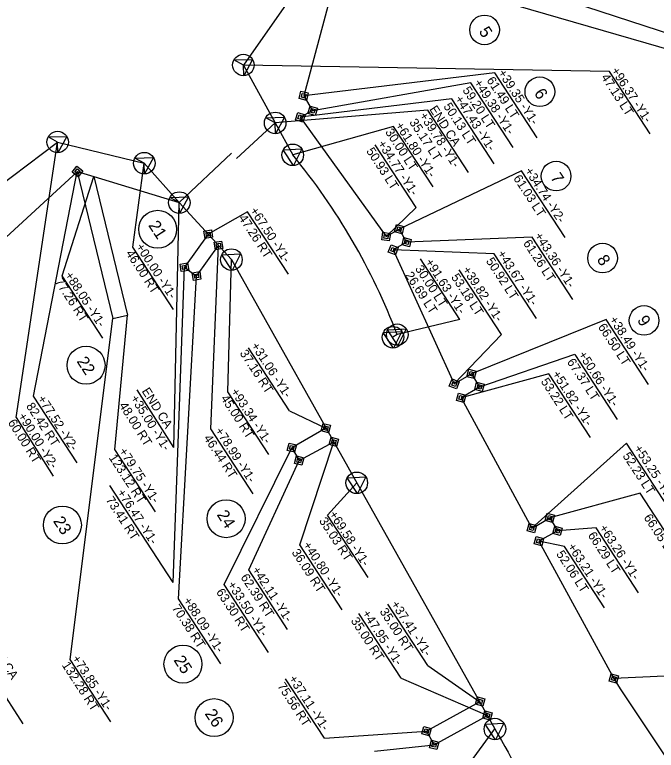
# Model space of a CAD drawing. Extents: x 1638966 to 1642158, y 841755 to 844938.
# Drawn here: x 1640306.3 to 1640735, y 843231.6 to 843723.1 of the extents above; entities that cross this region are included whole.
import ezdxf

# ---------------------------------------------------------------- set-up
doc = ezdxf.new("R2010")
doc.units = 0
for name, color, linetype in [('Exist Building', 7, 'Continuous'), ('Exist Guardrail Text', 7, 'Continuous'), ('Exist Other Culture Fence Line Text', 7, 'Continuous'), ('Exist Structure Major Deck Tunnel Box Culvert Text', 7, 'Continuous'), ('Exist Structure Minor Pipes CMP 18 Inch', 7, 'Continuous'), ('Exist Structure Minor Pipes CMP 18 Inch Text', 7, 'Continuous'), ('Exist Structure Minor Pipes CMP 24 Inch', 7, 'Continuous'), ('Exist Structure Minor Pipes RCP 24 Inch', 7, 'Continuous'), ('P_RDY_ROW_RW_CA_Lines', 7, 'Continuous'), ('Prop ROW Marker CA CELL', 7, 'Continuous'), ('Prop ROW Marker CELL', 7, 'Continuous')]:
    doc.layers.add(name, color=color, linetype=linetype)

msp = doc.modelspace()

# ---------------------------------------------------------------- linework, layer by layer
at = {"layer": 'Exist Building'}
for centre, radius in [((1640620.25, 843712.91), 9.91), ((1640657.19, 843671.65), 9.91), ((1640668.06, 843615.25), 9.91), ((1640401.81, 843579.7), 12.69), ((1640699.13, 843560.47), 9.91), ((1640726.79, 843518.8), 9.91), ((1640353.93, 843488.86), 12.69), ((1640447.56, 843386.31), 12.69), ((1640338.14, 843382.11), 12.69), ((1640418.7, 843289.14), 12.69), ((1640439.53, 843253.4), 12.69)]:
    msp.add_circle(centre, radius, dxfattribs=at)
at = {"layer": 'Exist Guardrail Text'}
for p, q in [((1640703.74, 843685.15), (1640459.09, 843689.48)), ((1640730.94, 843643.47), (1640703.74, 843685.15)), ((1640609.47, 843617.74), (1640582.27, 843659.42)), ((1640585.89, 843608.03), (1640559.48, 843648.51)), ((1640385.14, 843567.78), (1640392.88, 843623.89)), ((1640412.34, 843526.09), (1640385.14, 843567.78)), ((1640448.8, 843471.01), (1640451.09, 843559.48)), ((1640603.76, 843519.54), (1640577.34, 843560.02)), ((1640603.76, 843519.54), (1640561.9, 843509.3)), ((1640476, 843429.33), (1640448.8, 843471.01)), ((1640542.44, 843347.05), (1640515.24, 843388.74)), ((1640312.04, 843249.28), (1640271.05, 843312.1))]:
    msp.add_line(p, q, dxfattribs=at)
for points in [[(1640582.27, 843659.42), (1640480.35, 843650.79)], [(1640559.48, 843648.51), (1640492.08, 843629.44)], [(1640515.24, 843388.74), (1640534.84, 843410.29)], [(1640566.19, 843162.67), (1640627.16, 843245.8)]]:
    msp.add_lwpolyline(points, dxfattribs=at)
at = {"layer": 'Exist Other Culture Fence Line Text'}
for p, q in [((1640480.35, 843650.79), (1640492.08, 843629.44)), ((1640416.27, 843597.56), (1640451.09, 843559.48)), ((1640451.09, 843559.48), (1640627.16, 843245.8)), ((1640561.9, 843509.3), (1640559.02, 843507.57))]:
    msp.add_line(p, q, dxfattribs=at)
for centre, radius, start, end in [((1640160.09, 843356.15), 355, 34.9436, 34.9436), ((1640160.09, 843356.15), 430, 20.8649, 39.4616), ((1644817.57, 845597.08), 4805, 209.29724, 211.00035)]:
    msp.add_arc(centre, radius, start, end, dxfattribs=at)
at = {"layer": 'Exist Structure Major Deck Tunnel Box Culvert Text'}
for points in [[(1640480.35, 843650.79), (1640454.46, 843626.98)], [(1640416.27, 843597.56), (1640451.2, 843630.48)]]:
    msp.add_lwpolyline(points, dxfattribs=at)
at = {"layer": 'Exist Structure Minor Pipes CMP 18 Inch'}
for p, q in [((1640347.94, 843618.41), (1640371.82, 843520)), ((1640359.09, 843615), (1640381.54, 843522.35)), ((1640371.82, 843520), (1640381.54, 843522.35))]:
    msp.add_line(p, q, dxfattribs=at)
at = {"layer": 'Exist Structure Minor Pipes CMP 18 Inch Text'}
for p, q in [((1640781.19, 843688.57), (1640524.73, 843763.24)), ((1640788.22, 843695.73), (1640639.54, 843744.24)), ((1640338.03, 843548.66), (1640359.09, 843615)), ((1640365.23, 843506.98), (1640338.03, 843548.66)), ((1640343.42, 843292.29), (1640371.82, 843520)), ((1640373.23, 843432.53), (1640381.54, 843522.35)), ((1640400.43, 843390.84), (1640373.23, 843432.53)), ((1640370.62, 843250.6), (1640343.42, 843292.29))]:
    msp.add_line(p, q, dxfattribs=at)
at = {"layer": 'Exist Structure Minor Pipes CMP 24 Inch'}
for p, q in [((1640655.42, 843640.88), (1640627.13, 843684.24)), ((1640639.29, 843634.27), (1640611, 843677.63)), ((1640626.57, 843623.44), (1640598.28, 843666.8)), ((1640574.44, 843594.38), (1640547.24, 843636.06)), ((1640318.93, 843468.16), (1640347.94, 843618.41)), ((1640674.05, 843574.15), (1640644.98, 843618.71)), ((1640489.14, 843549.69), (1640461.94, 843591.37)), ((1640679.25, 843532.82), (1640652.05, 843574.51)), ((1640437.27, 843446.31), (1640442.46, 843568.92)), ((1640654.96, 843520.05), (1640626.67, 843563.41)), ((1640412.27, 843343.59), (1640419.69, 843554.33)), ((1640631.66, 843509.31), (1640603.37, 843552.67)), ((1640415.77, 843332.8), (1640427.78, 843548.48)), ((1640729.82, 843476.03), (1640701.53, 843519.39)), ((1640489.93, 843458.32), (1640462.42, 843500.47)), ((1640709.07, 843452.62), (1640680.78, 843495.98)), ((1640691.03, 843440.49), (1640663.14, 843483.23)), ((1640348.01, 843423.6), (1640318.93, 843468.16)), ((1640489.93, 843458.32), (1640514.16, 843446.9)), ((1640465.56, 843402.95), (1640437.27, 843446.31)), ((1640715.06, 843436.77), (1640651.87, 843380.03)), ((1640745.49, 843390.15), (1640715.06, 843436.77)), ((1640446.25, 843342.45), (1640491.39, 843433.78)), ((1640462.71, 843352.08), (1640496.39, 843425.11)), ((1640412.27, 843343.59), (1640369.87, 843408.56)), ((1640724.15, 843403.3), (1640663.85, 843386.92)), ((1640760.24, 843347.99), (1640724.15, 843403.3)), ((1640723.04, 843336.79), (1640694.74, 843380.15)), ((1640525.12, 843325.39), (1640496.83, 843368.75)), ((1640700.34, 843326.71), (1640673.61, 843367.66)), ((1640488.65, 843312.33), (1640462.71, 843352.08)), ((1640475.95, 843296.93), (1640446.25, 843342.45)), ((1640444.06, 843289.44), (1640415.77, 843332.8)), ((1640582.37, 843288.25), (1640555.65, 843329.2)), ((1640564.61, 843279.7), (1640536.32, 843323.06)), ((1640513.22, 843239.64), (1640487.28, 843279.39)), ((1640546.77, 843231), (1640586.56, 843235.12))]:
    msp.add_line(p, q, dxfattribs=at)
for points in [[(1640627.13, 843684.24), (1640499.38, 843668.98)], [(1640611, 843677.63), (1640505.38, 843658.87)], [(1640598.28, 843666.8), (1640497.12, 843654.53)], [(1640644.98, 843618.71), (1640563.27, 843579.75)], [(1640574.44, 843594.38), (1640554.45, 843574.83)], [(1640461.94, 843591.37), (1640435.59, 843576.43)], [(1640652.05, 843574.51), (1640568.19, 843571.13)], [(1640626.67, 843563.41), (1640559.21, 843566)], [(1640701.53, 843519.39), (1640611.58, 843483.05)], [(1640631.66, 843509.31), (1640599.98, 843476.41)], [(1640680.44, 843495.98), (1640616.76, 843474.3)], [(1640663.14, 843483.23), (1640604.56, 843467.07)], [(1640496.83, 843368.75), (1640519.55, 843437.67)], [(1640694.74, 843380.15), (1640669.03, 843378.18)], [(1640673.61, 843367.66), (1640656.59, 843371.25)], [(1640582.37, 843288.25), (1640616.98, 843263.95)], [(1640564.61, 843279.7), (1640622.14, 843254.75)], [(1640740.55, 843281.01), (1640706.65, 843279.59)], [(1640513.22, 843239.64), (1640581.46, 843244.36)]]:
    msp.add_lwpolyline(points, dxfattribs=at)
at = {"layer": 'Exist Structure Minor Pipes RCP 24 Inch'}
for p, q in [((1640528.84, 843778.51), (1640499.38, 843668.98)), ((1640499.38, 843668.98), (1640499.38, 843668.98)), ((1640499.38, 843668.98), (1640505.38, 843658.87)), ((1640505.38, 843658.87), (1640497.12, 843654.53)), ((1640505.38, 843658.87), (1640505.38, 843658.87)), ((1640497.12, 843654.53), (1640497.12, 843654.53)), ((1640497.12, 843654.53), (1640554.45, 843574.83)), ((1640269.63, 843546.21), (1640348.28, 843618.3)), ((1640347.94, 843618.41), (1640359.09, 843615)), ((1640348.28, 843618.3), (1640348.28, 843618.3)), ((1640359.09, 843615), (1640416.27, 843597.56)), ((1640554.45, 843574.83), (1640563.27, 843579.75)), ((1640563.27, 843579.75), (1640563.27, 843579.75)), ((1640563.27, 843579.75), (1640568.19, 843571.13)), ((1640435.59, 843576.43), (1640435.59, 843576.43)), ((1640554.45, 843574.83), (1640554.45, 843574.83)), ((1640442.46, 843568.92), (1640442.46, 843568.92)), ((1640568.19, 843571.13), (1640559.21, 843566)), ((1640568.19, 843571.13), (1640568.19, 843571.13)), ((1640559.21, 843566), (1640559.21, 843566)), ((1640559.21, 843566), (1640599.98, 843476.41)), ((1640419.69, 843554.33), (1640419.69, 843554.33)), ((1640427.78, 843548.48), (1640427.78, 843548.48)), ((1640599.98, 843476.41), (1640611.58, 843483.05)), ((1640611.58, 843483.05), (1640611.58, 843483.05)), ((1640611.58, 843483.05), (1640616.76, 843474.3)), ((1640599.98, 843476.41), (1640599.98, 843476.41)), ((1640616.76, 843474.3), (1640604.56, 843467.07)), ((1640616.77, 843474.5), (1640616.77, 843474.5)), ((1640604.56, 843467.07), (1640604.56, 843467.07)), ((1640604.56, 843467.07), (1640651.87, 843380.03)), ((1640514.16, 843446.9), (1640491.39, 843433.78)), ((1640514.16, 843446.9), (1640514.16, 843446.9)), ((1640496.39, 843425.11), (1640519.55, 843437.67)), ((1640519.55, 843437.67), (1640519.55, 843437.67)), ((1640491.39, 843433.78), (1640496.39, 843425.11)), ((1640491.39, 843433.78), (1640491.39, 843433.78)), ((1640496.39, 843425.11), (1640496.39, 843425.11)), ((1640655.09, 843381.73), (1640663.85, 843386.92)), ((1640663.85, 843386.92), (1640663.85, 843386.92)), ((1640663.85, 843386.92), (1640669.03, 843378.18)), ((1640651.87, 843380.03), (1640655.09, 843381.73)), ((1640651.87, 843380.03), (1640651.87, 843380.03)), ((1640669.03, 843378.18), (1640656.59, 843371.25)), ((1640669.03, 843378.18), (1640669.03, 843378.18)), ((1640656.59, 843371.25), (1640656.59, 843371.25)), ((1640656.59, 843371.25), (1640706.65, 843279.59)), ((1640706.65, 843279.5), (1640706.65, 843279.5)), ((1640617.32, 843264.14), (1640617.32, 843264.14)), ((1640622.14, 843254.75), (1640622.14, 843254.75)), ((1640581.46, 843244.36), (1640581.46, 843244.36)), ((1640586.56, 843235.12), (1640586.56, 843235.12))]:
    msp.add_line(p, q, dxfattribs=at)
for points in [[(1640497.54, 843672.07), (1640502.47, 843670.82), (1640501.21, 843665.88), (1640496.28, 843667.14)], [(1640498.46, 843670.53), (1640500.92, 843669.9), (1640500.3, 843667.43), (1640497.83, 843668.06)], [(1640503.71, 843662.05), (1640508.57, 843660.54), (1640507.06, 843655.68), (1640502.2, 843657.19)], [(1640495.45, 843657.72), (1640500.31, 843656.2), (1640498.79, 843651.35), (1640493.93, 843652.86)], [(1640496.29, 843656.13), (1640498.72, 843655.37), (1640497.96, 843652.94), (1640495.53, 843653.7)], [(1640504.55, 843660.46), (1640506.98, 843659.7), (1640506.22, 843657.27), (1640503.79, 843658.03)], [(1640347.8, 843621.87), (1640351.85, 843618.79), (1640348.76, 843614.74), (1640344.71, 843617.82)], [(1640348.04, 843620.09), (1640350.06, 843618.54), (1640348.52, 843616.52), (1640346.5, 843618.06)], [(1640561.45, 843582.86), (1640566.37, 843581.57), (1640565.08, 843576.65), (1640560.16, 843577.93)], [(1640432.67, 843578.53), (1640437.69, 843579.36), (1640438.52, 843574.34), (1640433.49, 843573.51)], [(1640434.13, 843577.48), (1640436.64, 843577.9), (1640437.05, 843575.38), (1640434.54, 843574.97)], [(1640552.35, 843577.76), (1640557.38, 843576.94), (1640556.55, 843571.91), (1640551.53, 843572.73)], [(1640562.36, 843581.31), (1640564.82, 843580.66), (1640564.18, 843578.2), (1640561.71, 843578.84)], [(1640553.4, 843576.3), (1640555.91, 843575.88), (1640555.5, 843573.37), (1640552.99, 843573.78)], [(1640566.37, 843574.23), (1640571.3, 843572.94), (1640570.01, 843568.02), (1640565.08, 843569.31)], [(1640567.28, 843572.68), (1640569.74, 843572.03), (1640569.1, 843569.57), (1640566.64, 843570.22)], [(1640439.53, 843571.02), (1640444.56, 843571.85), (1640445.38, 843566.83), (1640440.36, 843566)], [(1640441, 843569.97), (1640443.51, 843570.39), (1640443.92, 843567.88), (1640441.41, 843567.46)], [(1640557.73, 843569.28), (1640562.49, 843567.48), (1640560.69, 843562.72), (1640555.93, 843564.52)], [(1640558.47, 843567.64), (1640560.85, 843566.74), (1640559.95, 843564.36), (1640557.57, 843565.26)], [(1640416.76, 843556.43), (1640421.78, 843557.26), (1640422.61, 843552.24), (1640417.59, 843551.41)], [(1640418.22, 843555.38), (1640420.73, 843555.8), (1640421.15, 843553.28), (1640418.64, 843552.87)], [(1640424.86, 843550.58), (1640429.88, 843551.4), (1640430.71, 843546.38), (1640425.69, 843545.55)], [(1640426.32, 843549.53), (1640428.83, 843549.94), (1640429.25, 843547.43), (1640426.73, 843547.02)], [(1640609.76, 843486.16), (1640614.68, 843484.87), (1640613.4, 843479.95), (1640608.47, 843481.23)], [(1640610.67, 843484.6), (1640613.13, 843483.96), (1640612.49, 843481.5), (1640610.02, 843482.14)], [(1640598.49, 843479.69), (1640603.26, 843477.89), (1640601.46, 843473.13), (1640596.7, 843474.92)], [(1640599.24, 843478.05), (1640601.62, 843477.15), (1640600.72, 843474.77), (1640598.34, 843475.66)], [(1640614.95, 843477.61), (1640619.88, 843476.32), (1640618.59, 843471.4), (1640613.67, 843472.68)], [(1640615.86, 843476.06), (1640618.33, 843475.41), (1640617.68, 843472.95), (1640615.22, 843473.59)], [(1640602.74, 843470.18), (1640607.66, 843468.89), (1640606.38, 843463.97), (1640601.45, 843465.25)], [(1640603.65, 843468.63), (1640606.11, 843467.98), (1640605.47, 843465.52), (1640603, 843466.16)], [(1640512.34, 843450.01), (1640517.27, 843448.72), (1640515.98, 843443.8), (1640511.06, 843445.08)], [(1640513.25, 843448.46), (1640515.72, 843447.81), (1640515.07, 843445.35), (1640512.61, 843445.99)], [(1640517.73, 843440.77), (1640522.66, 843439.49), (1640521.37, 843434.56), (1640516.45, 843435.85)], [(1640489.57, 843436.88), (1640494.5, 843435.6), (1640493.21, 843430.67), (1640488.29, 843431.96)], [(1640490.48, 843435.33), (1640492.95, 843434.69), (1640492.3, 843432.23), (1640489.84, 843432.87)], [(1640518.64, 843439.22), (1640521.1, 843438.58), (1640520.46, 843436.11), (1640518, 843436.76)], [(1640494.57, 843428.22), (1640499.5, 843426.93), (1640498.21, 843422.01), (1640493.28, 843423.29)], [(1640495.48, 843426.66), (1640497.94, 843426.02), (1640497.3, 843423.56), (1640494.84, 843424.2)], [(1640662.03, 843390.03), (1640666.96, 843388.74), (1640665.67, 843383.82), (1640660.75, 843385.1)], [(1640662.94, 843388.48), (1640665.41, 843387.83), (1640664.76, 843385.37), (1640662.3, 843386.01)], [(1640650.05, 843383.13), (1640654.98, 843381.85), (1640653.69, 843376.92), (1640648.77, 843378.21)], [(1640650.96, 843381.58), (1640653.43, 843380.94), (1640652.78, 843378.47), (1640650.32, 843379.12)], [(1640667.21, 843381.29), (1640672.14, 843380), (1640670.85, 843375.07), (1640665.92, 843376.36)], [(1640668.12, 843379.73), (1640670.58, 843379.09), (1640669.94, 843376.63), (1640667.48, 843377.27)], [(1640654.78, 843374.36), (1640659.7, 843373.07), (1640658.41, 843368.15), (1640653.49, 843369.43)], [(1640655.68, 843372.81), (1640658.15, 843372.16), (1640657.5, 843369.7), (1640655.04, 843370.34)], [(1640704.83, 843282.61), (1640709.76, 843281.32), (1640708.47, 843276.4), (1640703.55, 843277.68)], [(1640705.74, 843281.05), (1640708.21, 843280.41), (1640707.56, 843277.95), (1640705.1, 843278.59)], [(1640615.5, 843267.25), (1640620.43, 843265.96), (1640619.14, 843261.03), (1640614.22, 843262.32)], [(1640616.41, 843265.69), (1640618.88, 843265.05), (1640618.23, 843262.59), (1640615.77, 843263.23)], [(1640620.32, 843257.86), (1640625.24, 843256.57), (1640623.96, 843251.65), (1640619.03, 843252.93)], [(1640621.23, 843256.3), (1640623.69, 843255.66), (1640623.05, 843253.2), (1640620.59, 843253.84)], [(1640579.64, 843247.46), (1640584.57, 843246.18), (1640583.28, 843241.25), (1640578.36, 843242.54)], [(1640580.55, 843245.91), (1640583.01, 843245.27), (1640582.37, 843242.81), (1640579.91, 843243.45)], [(1640584.74, 843238.23), (1640589.66, 843236.94), (1640588.37, 843232.02), (1640583.45, 843233.3)], [(1640585.65, 843236.68), (1640588.11, 843236.03), (1640587.47, 843233.57), (1640585, 843234.21)]]:
    msp.add_lwpolyline(points, close=True, dxfattribs=at)
for points in [[(1640435.59, 843576.43), (1640419.69, 843554.33), (1640427.78, 843548.48), (1640442.46, 843568.92)], [(1640706.65, 843279.5), (1640710.92, 843272.69), (1640777.02, 843173.29), (1640955.29, 842892.74)], [(1640616.98, 843263.95), (1640581.46, 843244.36), (1640586.56, 843235.12), (1640622.14, 843254.75)]]:
    msp.add_lwpolyline(points, dxfattribs=at)
at = {"layer": 'P_RDY_ROW_RW_CA_Lines'}
for p, q in [((1640577.95, 843859.33), (1640459.09, 843689.48)), ((1640459.09, 843689.48), (1640480.35, 843650.79)), ((1640293.13, 843606.47), (1640334.97, 843638.04)), ((1640334.97, 843638.04), (1640392.88, 843623.89)), ((1640392.88, 843623.89), (1640416.27, 843597.56))]:
    msp.add_line(p, q, dxfattribs=at)
at = {"layer": 'Prop ROW Marker CA CELL'}
for p, q in [((1640307.3, 843453.93), (1640334.97, 843638.04)), ((1640412.5, 843433.97), (1640416.27, 843597.56)), ((1640412.5, 843433.97), (1640388.17, 843472.43)), ((1640307.3, 843453.93), (1640332.06, 843414.79))]:
    msp.add_line(p, q, dxfattribs=at)
at = {"layer": 'Prop ROW Marker CELL'}
for p, q in [((1640452.75, 843692.91), (1640465.22, 843693.26)), ((1640459.09, 843689.48), (1640452.75, 843692.91)), ((1640465.22, 843693.26), (1640459.31, 843682.27)), ((1640459.31, 843682.27), (1640459.09, 843689.48)), ((1640474, 843654.22), (1640486.47, 843654.58)), ((1640480.35, 843650.79), (1640474, 843654.22)), ((1640486.47, 843654.58), (1640480.57, 843643.58)), ((1640480.57, 843643.58), (1640480.35, 843650.79)), ((1640328.63, 843641.47), (1640341.1, 843641.82)), ((1640334.97, 843638.04), (1640328.63, 843641.47)), ((1640341.1, 843641.82), (1640335.19, 843630.83)), ((1640335.19, 843630.83), (1640334.97, 843638.04)), ((1640386.54, 843627.32), (1640399.01, 843627.67)), ((1640392.88, 843623.89), (1640386.54, 843627.32)), ((1640399.01, 843627.67), (1640393.1, 843616.68)), ((1640492.08, 843629.44), (1640492.08, 843629.44)), ((1640393.1, 843616.68), (1640392.88, 843623.89)), ((1640409.92, 843600.99), (1640422.4, 843601.34)), ((1640416.27, 843597.56), (1640409.92, 843600.99)), ((1640416.49, 843590.35), (1640416.27, 843597.56)), ((1640422.4, 843601.34), (1640416.49, 843590.35)), ((1640451.09, 843559.48), (1640451.09, 843559.48)), ((1640561.9, 843509.3), (1640561.9, 843509.3)), ((1640559.02, 843507.57), (1640559.02, 843507.57)), ((1640534.84, 843410.29), (1640534.84, 843410.29)), ((1640627.16, 843245.8), (1640627.16, 843245.8))]:
    msp.add_line(p, q, dxfattribs=at)
for points in [[(1640485.65, 843632.71), (1640498.11, 843633.38), (1640492.48, 843622.24)], [(1640444.66, 843562.75), (1640457.12, 843563.42), (1640451.49, 843552.28)], [(1640552.59, 843510.84), (1640565.05, 843511.5), (1640559.42, 843500.37)], [(1640555.47, 843512.57), (1640567.93, 843513.24), (1640562.3, 843502.1)], [(1640528.41, 843413.56), (1640540.87, 843414.22), (1640535.24, 843403.09)], [(1640620.73, 843249.07), (1640633.19, 843249.74), (1640627.56, 843238.6)]]:
    msp.add_lwpolyline(points, close=True, dxfattribs=at)
for centre in [(1640459.09, 843689.48), (1640480.35, 843650.79), (1640334.97, 843638.04), (1640492.08, 843629.44), (1640392.88, 843623.89), (1640416.27, 843597.56), (1640451.09, 843559.48), (1640559.02, 843507.57), (1640561.9, 843509.3), (1640534.84, 843410.29), (1640627.16, 843245.8)]:
    msp.add_circle(centre, 7.2, dxfattribs=at)

# ---------------------------------------------------------------- texts
at = {"layer": 'Exist Building'}
for s, p in [('5', (1640616.1, 843711.94)), ('6', (1640653.04, 843670.68)), ('7', (1640663.91, 843614.29)), ('21', (1640395.3, 843582.36)), ('8', (1640694.98, 843559.5)), ('9', (1640721.9, 843518.98)), ('22', (1640347.42, 843491.52)), ('24', (1640441.05, 843388.97)), ('23', (1640331.64, 843384.77)), ('25', (1640412.19, 843291.8)), ('26', (1640433.02, 843256.06))]:
    msp.add_text(s, height=8, rotation=303.0906, dxfattribs=at).set_placement(p)
at = {"layer": 'Exist Guardrail Text'}
for s, p in [('+96.37 -Y1-', (1640704.57, 843685.7)), ('47.13 LT', (1640697.87, 843681.33)), ('END CA', (1640583.11, 843659.97)), ('+39.78 -Y1-', (1640576.41, 843655.6)), ('35.17 LT', (1640569.71, 843651.23)), ('30.00 LT', (1640553.62, 843644.69)), ('+61.80 -Y1-', (1640560.32, 843649.06)), ('+00.00 -Y1-', (1640386.96, 843567.98)), ('46.00 RT', (1640380.26, 843563.6)), ('+91.63 -Y1-', (1640580.26, 843557.77)), ('30.00 LT', (1640573.56, 843553.4)), ('26.69 LT', (1640566.86, 843549.03)), ('+93.34 -Y1-', (1640450.37, 843471.16)), ('45.00 RT', (1640443.67, 843466.79)), ('+69.58 -Y1-', (1640516.08, 843389.28)), ('35.03 RT', (1640509.38, 843384.91)), ('BEGIN CA', (1640283.14, 843310.44))]:
    msp.add_text(s, height=6, rotation=303.1259, dxfattribs=at).set_placement(p)
at = {"layer": 'Exist Structure Minor Pipes CMP 18 Inch Text'}
for s, p in [('+88.05 -Y1-', (1640339.5, 843549.05)), ('77.26 RT', (1640332.8, 843544.68)), ('+79.75 -Y1-', (1640375.62, 843431.44)), ('123.12 RT', (1640368.92, 843427.07)), ('+73.85 -Y1-', (1640344.26, 843292.83)), ('132.28 RT', (1640337.56, 843288.46))]:
    msp.add_text(s, height=6, rotation=303.1259, dxfattribs=at).set_placement(p)
at = {"layer": 'Exist Structure Minor Pipes CMP 24 Inch'}
for s, p in [('+39.35 -Y1-', (1640628.93, 843684.22)), ('61.49 LT', (1640621.4, 843679.31)), ('+49.38 -Y1-', (1640612.8, 843677.62)), ('59.20 LT', (1640605.26, 843672.7)), ('+47.43 -Y1-', (1640600.08, 843666.78)), ('50.13 LT', (1640592.54, 843661.87)), ('+34.77 -Y1-', (1640548.5, 843636.88)), ('50.93 LT', (1640540.96, 843631.97)), ('+34.74 -Y2-', (1640646.78, 843618.69)), ('61.03 LT', (1640639.24, 843613.77)), ('+67.50 -Y1-', (1640463.2, 843592.19)), ('47.26 RT', (1640455.66, 843587.28)), ('61.26 LT', (1640645.77, 843570.41)), ('+43.36 -Y1-', (1640653.31, 843575.33)), ('+43.67 -Y1-', (1640628.47, 843563.39)), ('50.92 LT', (1640620.93, 843558.47)), ('+39.82 -Y1-', (1640605.17, 843552.65)), ('53.18 LT', (1640597.63, 843547.73)), ('+38.49 -Y1-', (1640703.33, 843519.37)), ('66.50 LT', (1640695.79, 843514.45)), ('37.16 RT', (1640456.4, 843496.91)), ('+31.06 -Y1-', (1640463.94, 843501.82)), ('+50.66 -Y1-', (1640682.58, 843495.96)), ('67.37 LT', (1640675.05, 843491.04)), ('+51.82 -Y1-', (1640665.13, 843482.92)), ('53.22 LT', (1640657.6, 843478)), ('+77.52 -Y2-', (1640321.18, 843466.44)), ('82.42 RT', (1640313.64, 843461.52)), ('+78.99 -Y1-', (1640439.83, 843445.1)), ('46.44 RT', (1640432.29, 843440.19)), ('+53.25 -Y1-', (1640719.79, 843433.24)), ('52.23 LT', (1640712.25, 843428.32)), ('+76.47 -Y1-', (1640374.4, 843403.8)), ('73.41 RT', (1640366.87, 843398.89)), ('66.05 LT', (1640726.36, 843387.11)), ('+63.26 -Y1-', (1640696.55, 843380.13)), ('66.29 LT', (1640689.01, 843375.21)), ('36.09 RT', (1640491.09, 843363.81)), ('+40.80 -Y1-', (1640498.63, 843368.73)), ('+63.21 -Y1-', (1640675.42, 843367.64)), ('52.06 LT', (1640667.88, 843362.72)), ('+42.11 -Y1-', (1640464.52, 843352.06)), ('62.39 RT', (1640456.98, 843347.15)), ('+33.50 -Y1-', (1640448.17, 843342.22)), ('63.30 RT', (1640440.63, 843337.31)), ('+88.09 -Y1-', (1640418.62, 843331.55)), ('70.38 RT', (1640411.08, 843326.63)), ('35.00 RT', (1640549.91, 843324.27)), ('+37.41 -Y1-', (1640557.45, 843329.18)), ('+47.95 -Y1-', (1640538.12, 843323.04)), ('35.00 RT', (1640530.58, 843318.12)), ('75.56 RT', (1640481.54, 843274.45)), ('+37.11 -Y1-', (1640489.08, 843279.37))]:
    msp.add_text(s, height=6, rotation=303.1259, dxfattribs=at).set_placement(p)
at = {"layer": 'Prop ROW Marker CA CELL'}
for s, p in [('END CA', (1640390.97, 843471.6)), ('+35.00 -Y1-', (1640383.36, 843466.78)), ('48.00 RT', (1640375.75, 843461.97)), ('+90.00 -Y2-', (1640308.23, 843454.8)), ('60.00 RT', (1640301.47, 843450.53))]:
    msp.add_text(s, height=6, rotation=302.3172, dxfattribs=at).set_placement(p)

doc.saveas('drawing.dxf')
